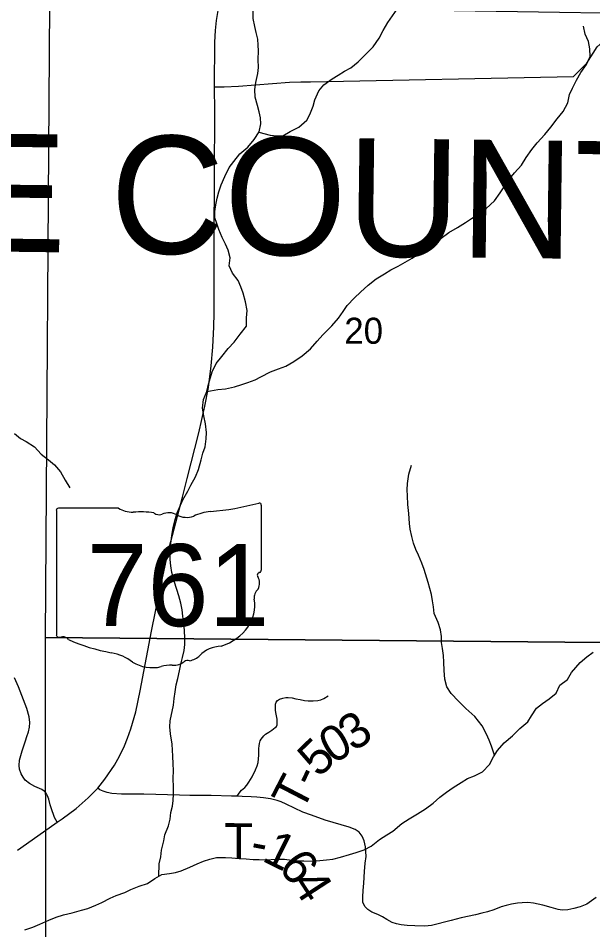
# Model space of a CAD drawing. Extents: x 0 to 191, y 0 to 55.
# Drawn here: x 146.011 to 146.473, y 24.084 to 24.816 of the extents above; entities that cross this region are included whole.
import ezdxf

# ---------------------------------------------------------------- set-up
doc = ezdxf.new("R2010")
doc.units = 0
for name, color, linetype in [('GM_X_Corporation', 7, 'Continuous'), ('GM_X_County_Road', 7, 'Continuous'), ('GM_X_County_Text', 7, 'Continuous'), ('GM_X_Minor_River', 7, 'Continuous'), ('GM_X_Section_Text', 7, 'Continuous'), ('GM_X_State_Location', 7, 'Continuous'), ('GM_X_State_Route', 7, 'Continuous'), ('GM_X_State_Shield', 7, 'Continuous'), ('GM_X_Township_Road', 7, 'Continuous'), ('GM_X_Township_Road_Text', 7, 'Continuous')]:
    doc.layers.add(name, color=color, linetype=linetype)

msp = doc.modelspace()

# ---------------------------------------------------------------- linework, layer by layer
at = {"layer": 'GM_X_Corporation'}
for points in [[(146.03675, 24.82762), (146.03933, 24.82759), (146.54827, 24.81955), (146.54508, 24.6158), (146.54032, 24.31446), (146.03321, 24.31897)], [(146.03321, 24.31897), (146.54032, 24.31446), (146.53796, 24.10543), (146.53621, 23.80622), (146.0338, 23.81325)]]:
    msp.add_lwpolyline(points, close=True, dxfattribs=at)
at = {"layer": 'GM_X_County_Road'}
for points in [[(146.0371, 24.18454), (146.03603, 24.18895), (146.03496, 24.19162), (146.03373, 24.19387), (146.03218, 24.19558), (146.0302, 24.19686), (146.02464, 24.19932), (146.02041, 24.20152), (146.01699, 24.20419), (146.01517, 24.20665), (146.01356, 24.20949), (146.01233, 24.21318), (146.01201, 24.21612), (146.01239, 24.22046), (146.01453, 24.22789), (146.0172, 24.23586), (146.01832, 24.23929), (146.0195, 24.24319), (146.02025, 24.24688), (146.02057, 24.25057), (146.01998, 24.25507), (146.01827, 24.26186), (146.01164, 24.27914), (146.00837, 24.28652)], [(146.04266, 24.17063), (146.04058, 24.17423), (146.03769, 24.1821), (146.0371, 24.18454)]]:
    msp.add_lwpolyline(points, dxfattribs=at)
at = {"layer": 'GM_X_Minor_River'}
for points in [[(146.20647, 24.73144), (146.20608, 24.73637), (146.20493, 24.74112), (146.20359, 24.74624), (146.20187, 24.75307), (146.20147, 24.75915), (146.20241, 24.76485), (146.20391, 24.77207), (146.20446, 24.77682), (146.20426, 24.78327), (146.20443, 24.79011), (146.20423, 24.79486), (146.20384, 24.7996), (146.2025, 24.80492), (146.20154, 24.80966), (146.2002, 24.81611), (146.20018, 24.82238), (146.20165, 24.82567)], [(146.20485, 24.72498), (146.21389, 24.72253), (146.21921, 24.72179), (146.22395, 24.72199), (146.23001, 24.72543), (146.23684, 24.72887), (146.24327, 24.7344), (146.24573, 24.73916), (146.24837, 24.74581), (146.24987, 24.75075), (146.25289, 24.75798), (146.25705, 24.76293), (146.26368, 24.7677), (146.26842, 24.77056), (146.27353, 24.77381), (146.27865, 24.77667), (146.28471, 24.78125), (146.29096, 24.78772), (146.29663, 24.79344), (146.30155, 24.80029), (146.30457, 24.80657), (146.30835, 24.81285), (146.31581, 24.82378)], [(146.16304, 24.51665), (146.17173, 24.51821), (146.17799, 24.5186), (146.18519, 24.52015), (146.19107, 24.52226), (146.19581, 24.52379), (146.20168, 24.5259), (146.20642, 24.52838), (146.214, 24.5324), (146.22063, 24.5347), (146.22651, 24.53681), (146.23295, 24.54063), (146.23958, 24.54521), (146.2462, 24.55093), (146.2515, 24.55702), (146.25623, 24.56217), (146.26342, 24.56941), (146.26872, 24.5755), (146.2725, 24.58083), (146.27571, 24.58559), (146.28158, 24.59169), (146.2865, 24.59646), (146.29275, 24.60198), (146.29899, 24.60694), (146.30582, 24.61114), (146.31093, 24.6142), (146.3168, 24.61726), (146.32249, 24.62031), (146.32798, 24.62375), (146.33291, 24.6268), (146.33821, 24.63043), (146.34522, 24.63501), (146.35128, 24.63959), (146.35753, 24.64417), (146.36435, 24.64818), (146.37079, 24.65238), (146.37571, 24.65562), (146.38196, 24.65925), (146.38746, 24.66345), (146.39427, 24.66973), (146.39862, 24.67602), (146.40183, 24.68096), (146.40524, 24.68591), (146.41034, 24.6922), (146.41583, 24.69829), (146.41961, 24.70457), (146.42415, 24.71104), (146.4285, 24.71619), (146.43474, 24.72304), (146.43947, 24.72875), (146.44458, 24.73561), (146.44949, 24.74151), (146.45308, 24.74855), (146.45458, 24.75501), (146.45685, 24.76033), (146.46006, 24.76661), (146.46365, 24.77289), (146.46819, 24.77917), (146.47102, 24.78563), (146.47081, 24.79171), (146.46966, 24.79759), (146.46699, 24.80366), (146.46584, 24.80992)], [(146.12428, 24.1271), (146.12454, 24.13696), (146.12585, 24.14266), (146.1266, 24.14798), (146.12829, 24.15558), (146.12922, 24.16034), (146.13224, 24.16756), (146.13336, 24.17289), (146.13411, 24.1784), (146.13523, 24.18334), (146.13579, 24.18809), (146.13616, 24.19303), (146.13614, 24.19854), (146.13593, 24.20557), (146.13611, 24.21203), (146.1359, 24.21735), (146.13551, 24.22362), (146.1351, 24.23311), (146.13375, 24.24147), (146.13317, 24.24716), (146.13354, 24.25191), (146.13616, 24.26446), (146.13671, 24.26997), (146.13746, 24.27529), (146.13839, 24.281), (146.13971, 24.28594), (146.14102, 24.29221), (146.14214, 24.29754), (146.14346, 24.30286), (146.14477, 24.30856), (146.14533, 24.31332), (146.14531, 24.31807), (146.14492, 24.3249), (146.14434, 24.32965), (146.14375, 24.33611), (146.14317, 24.34105), (146.14201, 24.34655), (146.14048, 24.35225), (146.13876, 24.35756), (146.13665, 24.3642), (146.13474, 24.37123), (146.13397, 24.37636), (146.13357, 24.38148), (146.13356, 24.38794), (146.13411, 24.3944), (146.13485, 24.40087), (146.13578, 24.40714), (146.13747, 24.4136), (146.13916, 24.41912), (146.14369, 24.42939), (146.14766, 24.43644), (146.15011, 24.44138), (146.15389, 24.44805), (146.15615, 24.45394), (146.1584, 24.46174), (146.15972, 24.46687), (146.1616, 24.4722), (146.16234, 24.47847), (146.16271, 24.4836), (146.16174, 24.49044), (146.1604, 24.49708), (146.15943, 24.50316), (146.16036, 24.51), (146.163, 24.51647), (146.16432, 24.52236), (146.16582, 24.52768), (146.16733, 24.53244), (146.17053, 24.53891), (146.17488, 24.54462), (146.17999, 24.5511), (146.18491, 24.55624), (146.18982, 24.56253), (146.19493, 24.569), (146.19472, 24.57584), (146.19528, 24.58154), (146.19412, 24.58856), (146.19202, 24.59558), (146.1903, 24.60071), (146.1882, 24.60564), (146.18344, 24.6117), (146.18077, 24.61758), (146.1817, 24.62385), (146.17998, 24.63012), (146.17788, 24.63486), (146.17521, 24.64017), (146.17253, 24.64662), (146.171, 24.65136), (146.16947, 24.65611), (146.16946, 24.66105), (146.17021, 24.66656), (146.17114, 24.67188), (146.17246, 24.67701), (146.17453, 24.68252), (146.17736, 24.68918), (146.18095, 24.69641), (146.18454, 24.70136), (146.18946, 24.70745), (146.19589, 24.71279), (146.201, 24.71907), (146.20497, 24.72516), (146.20647, 24.73144)], [(146.00827, 24.48273), (146.01303, 24.47875), (146.01778, 24.4763), (146.02443, 24.47195), (146.02976, 24.46608), (146.03565, 24.46172), (146.04059, 24.45775), (146.04535, 24.45188), (146.04916, 24.44524), (146.05278, 24.43917)], [(146.39428, 24.22443), (146.39181, 24.23167), (146.3899, 24.23641), (146.38761, 24.24134), (146.38417, 24.24798), (146.37827, 24.25556), (146.37105, 24.26199), (146.36534, 24.26767), (146.35925, 24.27392), (146.35582, 24.27923), (146.35429, 24.2855), (146.3537, 24.29252), (146.35331, 24.29898), (146.3531, 24.30449), (146.35233, 24.31), (146.35156, 24.31493), (146.35154, 24.31968), (146.35077, 24.32519), (146.34886, 24.33107), (146.3458, 24.33828), (146.34503, 24.34341), (146.34426, 24.34835), (146.34349, 24.35347), (146.34214, 24.35822), (146.3408, 24.36315), (146.33774, 24.3734), (146.33564, 24.37871), (146.33297, 24.38497), (146.33087, 24.38972), (146.32915, 24.39465), (146.32781, 24.39997), (146.32627, 24.40585), (146.32588, 24.4106), (146.32529, 24.41839), (146.32451, 24.42579), (146.32411, 24.43282), (146.32391, 24.43757), (146.32428, 24.44251), (146.3254, 24.45011), (146.32746, 24.45734)], [(146.41454, 24.2458), (146.42097, 24.25114), (146.42399, 24.25609), (146.42796, 24.26218), (146.43289, 24.26599), (146.438, 24.26962), (146.44368, 24.2742), (146.4467, 24.28048), (146.45276, 24.28506), (146.45616, 24.29077), (146.46316, 24.29877), (146.46846, 24.30334), (146.47338, 24.30716)], [(146.01672, 24.084), (146.02298, 24.0863), (146.02866, 24.08859), (146.03586, 24.09185), (146.04193, 24.09433), (146.0478, 24.09606), (146.05463, 24.09779), (146.06221, 24.09991), (146.06714, 24.10125), (146.07378, 24.10393), (146.07851, 24.10604), (146.08534, 24.10948), (146.09007, 24.11158), (146.0969, 24.11407), (146.10182, 24.11637), (146.10865, 24.11924), (146.11528, 24.12135), (146.12115, 24.12536), (146.12665, 24.12842), (146.13291, 24.12939), (146.13765, 24.13016), (146.14239, 24.13151), (146.14921, 24.13438), (146.15508, 24.13706), (146.1602, 24.13916), (146.16532, 24.14089), (146.17082, 24.14205), (146.17784, 24.14226), (146.18296, 24.1419), (146.18903, 24.14135), (146.19454, 24.14098), (146.20023, 24.14062), (146.20497, 24.14045), (146.21123, 24.14028), (146.21787, 24.14087), (146.22527, 24.14089), (146.23116, 24.13996), (146.2359, 24.13941), (146.24083, 24.13942), (146.24785, 24.13926), (146.25373, 24.13966), (146.25905, 24.14024), (146.26417, 24.14083), (146.27042, 24.14237), (146.27763, 24.14467), (146.28293, 24.14621), (146.28938, 24.14832), (146.29506, 24.15138), (146.30169, 24.15672), (146.30756, 24.16035), (146.31249, 24.1634), (146.31968, 24.1695), (146.32555, 24.17313), (146.33237, 24.17733), (146.33881, 24.18134), (146.34487, 24.18573), (146.35017, 24.19069), (146.35566, 24.19469), (146.36097, 24.19832), (146.36741, 24.20233), (146.37252, 24.20558), (146.37821, 24.20788), (146.38465, 24.21094), (146.39014, 24.21684), (146.39335, 24.22293), (146.39656, 24.22807), (146.40204, 24.23436), (146.40867, 24.23989), (146.41454, 24.2458)]]:
    msp.add_lwpolyline(points, dxfattribs=at)
at = {"layer": 'GM_X_State_Route'}
msp.add_lwpolyline([(146.01082, 24.14813), (146.02697, 24.15949), (146.04266, 24.17063), (146.04655, 24.17318), (146.05777, 24.18155), (146.06756, 24.19022), (146.07534, 24.19785), (146.08087, 24.20502), (146.08864, 24.21646), (146.09261, 24.22364), (146.09672, 24.23179), (146.09926, 24.23792), (146.10195, 24.24554), (146.10576, 24.2593), (146.10928, 24.27612), (146.11855, 24.32397), (146.12505, 24.35694), (146.13043, 24.38146), (146.13275, 24.39088), (146.14329, 24.4317), (146.14703, 24.44658), (146.15638, 24.48321), (146.16131, 24.50467), (146.16415, 24.51984), (146.16654, 24.53711), (146.16781, 24.55214), (146.16849, 24.56859), (146.16871, 24.57943), (146.16879, 24.59408), (146.16886, 24.61546), (146.16886, 24.64028), (146.16916, 24.68955), (146.16938, 24.74151), (146.16915, 24.76124), (146.16944, 24.79723), (146.16985, 24.80658), (146.17069, 24.81447), (146.17257, 24.82593)], dxfattribs=at)
at = {"layer": 'GM_X_State_Shield'}
for p, q in [((146.09184, 24.42277), (146.04358, 24.42277)), ((146.20675, 24.37291), (146.20675, 24.42525)), ((146.04196, 24.42105), (146.04196, 24.32099)), ((146.20673, 24.37292), (146.20675, 24.37291))]:
    msp.add_line(p, q, dxfattribs=at)
for centre, major_axis, start_param, end_param in [((146.04384, 24.42126), (0.00191, 0), 1.712693, 3.28349), ((146.10333, 24.43439), (0.01852, 0), 4.042523, 4.731795), ((146.14805, 24.55919), (0.17476, 0), 4.814394, 5.042369), ((146.20492, 24.42547), (0.00183, 0), 6.141152, 7.989035), ((146.10947, 24.3666), (0.06648, 0), 1.404758, 1.657858), ((146.12456, 24.42178), (0.00534, 0), 3.836095, 5.185415), ((146.13241, 24.41022), (0.01111, 0), 0.950623, 2.079405), ((146.14674, 24.42608), (0.01336, 0), 4.081561, 5.145723), ((146.17034, 24.39221), (0.03516, 0), 1.699011, 2.107814), ((146.20632, 24.36907), (0.00284, 0), 1.883978, 3.671073), ((146.20479, 24.37271), (0.00196, 0), 5.05454, 6.418171), ((146.18826, 24.36245), (0.01704, 0), 5.934695, 6.695948), ((146.21332, 24.351), (0.0124, 0), 2.387724, 3.262537), ((146.15784, 24.34434), (0.04371, 0), 5.101752, 6.440018), ((146.04386, 24.32077), (0.00193, 0), 3.00124, 4.508301), ((146.04415, 24.33101), (0.0147, 0), 4.665946, 4.897461), ((146.04716, 24.31522), (0.0053, 0), 0.519207, 1.627899), ((146.11407, 24.40512), (0.1262, 0), 4.195997, 4.488961), ((146.17627, 24.2929), (0.02394, 0), 1.647645, 2.488434), ((146.07645, 24.27604), (0.03949, 0), 0.823519, 1.323587), ((146.14594, 24.31129), (0.01412, 0), 4.937069, 5.64225), ((146.11915, 24.31472), (0.02506, 0), 4.026481, 4.996735), ((146.13546, 24.30723), (0.01335, 0), 4.691044, 5.507374), ((146.14754, 24.29754), (0.00376, 0), 1.147584, 2.315152), ((146.13363, 24.28013), (0.02059, 0), 1.495662, 1.94098)]:
    msp.add_ellipse(centre, major_axis=major_axis, ratio=0.8, start_param=start_param, end_param=end_param, dxfattribs=at)
at = {"layer": 'GM_X_Township_Road'}
for points in [[(146.24633, 24.7654), (146.45762, 24.7695), (146.4684, 24.78017), (146.4767, 24.79329), (146.4905, 24.80548), (146.50868, 24.81199), (146.52044, 24.81165), (146.54424, 24.81196), (146.5609, 24.81265), (146.56714, 24.81248), (146.57611, 24.81262), (146.58259, 24.81248), (146.58869, 24.81182), (146.59971, 24.81054), (146.60612, 24.80908), (146.61142, 24.80756), (146.61666, 24.8052), (146.61939, 24.8033), (146.62144, 24.80132), (146.62532, 24.79692), (146.62569, 24.79661)], [(146.16915, 24.76124), (146.17696, 24.76124), (146.18849, 24.76195), (146.22939, 24.76507), (146.23859, 24.76525), (146.24633, 24.7654)], [(146.18741, 24.19141), (146.18883, 24.19373), (146.19092, 24.19617), (146.1934, 24.19848), (146.19502, 24.20036), (146.1968, 24.2027), (146.19939, 24.20706), (146.20212, 24.21267), (146.20333, 24.21574), (146.2042, 24.21859), (146.20454, 24.22149), (146.2047, 24.22448), (146.20485, 24.22724), (146.20479, 24.22963), (146.20488, 24.23191), (146.20524, 24.23377), (146.20592, 24.23577), (146.20671, 24.23724), (146.20772, 24.23867), (146.20876, 24.23989), (146.21015, 24.24121), (146.21136, 24.24214), (146.21279, 24.24298), (146.21524, 24.2445), (146.21786, 24.24653), (146.21885, 24.24746), (146.21936, 24.24882), (146.21955, 24.25079), (146.2195, 24.25321), (146.21865, 24.25744), (146.21826, 24.26014), (146.21804, 24.26299), (146.21817, 24.26544), (146.21865, 24.26693), (146.21964, 24.26825), (146.22139, 24.26941), (146.22389, 24.27025), (146.22648, 24.27079), (146.22843, 24.27076), (146.23141, 24.27034), (146.23457, 24.26972), (146.23806, 24.26901), (146.24153, 24.26839), (146.24444, 24.26816), (146.2484, 24.26803), (146.25206, 24.2682), (146.2546, 24.26882), (146.25699, 24.26986), (146.2605, 24.27198)], [(146.1122, 24.19294), (146.11126, 24.19296), (146.10548, 24.19314), (146.09423, 24.19314), (146.08661, 24.19361), (146.08274, 24.19427), (146.0797, 24.1954), (146.07703, 24.19665), (146.07534, 24.19785)], [(146.47591, 24.10997), (146.47222, 24.10729), (146.46841, 24.10479), (146.46293, 24.10264), (146.45797, 24.10108), (146.45299, 24.10008), (146.44852, 24.0999), (146.44543, 24.10038), (146.43971, 24.10193), (146.43298, 24.10395), (146.4256, 24.1055), (146.42084, 24.10592), (146.41637, 24.1058), (146.41256, 24.10538), (146.4078, 24.10455), (146.40357, 24.10354), (146.39958, 24.10241), (146.39351, 24.1002), (146.38845, 24.09865), (146.38405, 24.09752), (146.37893, 24.09621), (146.36739, 24.0936), (146.35924, 24.09167), (146.34352, 24.08745), (146.33826, 24.08693), (146.33005, 24.08716), (146.32409, 24.08752), (146.31903, 24.088), (146.31528, 24.08883), (146.31195, 24.0899), (146.30766, 24.09228), (146.30403, 24.09455), (146.3004, 24.09639), (146.2957, 24.09812), (146.2923, 24.10038), (146.28992, 24.10288), (146.28843, 24.10639), (146.28831, 24.11062), (146.28855, 24.11574), (146.28903, 24.12158), (146.28956, 24.13098), (146.29016, 24.13753), (146.29099, 24.14307), (146.29087, 24.14712), (146.29046, 24.15069), (146.2895, 24.15569), (146.2879, 24.15938), (146.28534, 24.16242), (146.28206, 24.16456), (146.27742, 24.16646), (146.25813, 24.17218), (146.24718, 24.17611), (146.24021, 24.17867), (146.23328, 24.18174), (146.22681, 24.18498), (146.22265, 24.18683), (146.2194, 24.188), (146.21407, 24.18927), (146.20837, 24.19005), (146.20324, 24.1907), (146.19857, 24.19086), (146.19139, 24.19111), (146.18741, 24.19141), (146.18288, 24.19135), (146.16645, 24.19209), (146.1493, 24.192), (146.14085, 24.1923), (146.1122, 24.19294)]]:
    msp.add_lwpolyline(points, dxfattribs=at)

# ---------------------------------------------------------------- texts
at = {"layer": 'GM_X_County_Text'}
msp.add_text('NOBLE COUNTY', height=0.094697, rotation=359.28458, dxfattribs=at).set_placement((145.62033, 24.63362))
at = {"layer": 'GM_X_Section_Text'}
msp.add_text('20', height=0.020928, rotation=0.00001, dxfattribs=at).set_placement((146.27345, 24.55487))
at = {"layer": 'GM_X_State_Location'}
for s in ['s', 'r']:
    msp.add_text(s, height=0.0000947, dxfattribs=at).set_placement((146.1225, 24.36437))
msp.add_text('761', height=0.0000947, rotation=0.00001, dxfattribs=at).set_placement((146.08907, 24.35748))
at = {"layer": 'GM_X_State_Shield'}
msp.add_text('761', height=0.065918, dxfattribs=at).set_placement((146.06624, 24.32805))
at = {"layer": 'GM_X_Township_Road_Text'}
for s, rotation, p in [('3', 33.90075, (146.28077, 24.22661)), ('0', 30.34971, (146.26404, 24.21675)), ('5', 44.43331, (146.25301, 24.20561)), ('T', 62.59735, (146.23926, 24.17777)), ('-', 63.74394, (146.24932, 24.19719)), ('T', 359.86286, (146.17697, 24.14136)), ('1', 333.63276, (146.20637, 24.13995)), ('-', 349.4096, (146.19686, 24.14144)), ('6', 309.39047, (146.21958, 24.13414)), ('4', 303.00882, (146.23019, 24.12129))]:
    msp.add_text(s, height=0.02841, rotation=rotation, dxfattribs=at).set_placement(p)

doc.saveas('drawing.dxf')
